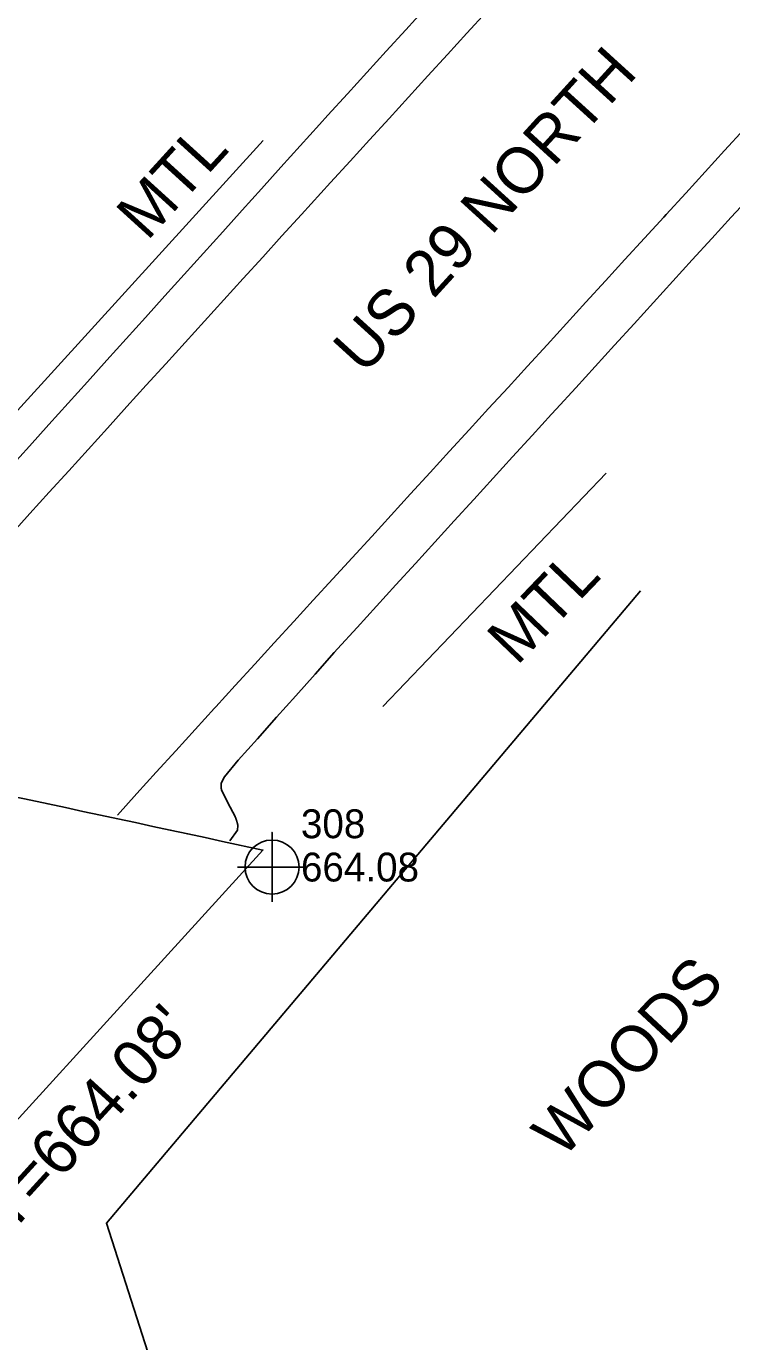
# Model space of a CAD drawing. Extents: x 1806071 to 1809844, y 912722 to 917035.
# Drawn here: x 1809224.9 to 1809286, y 916067.4 to 916181.4 of the extents above; entities that cross this region are included whole.
import ezdxf

# ---------------------------------------------------------------- set-up
doc = ezdxf.new("R2010")
doc.units = 0
for name, color, linetype in [('Exist Guardrail', 7, 'Continuous'), ('Exist Guardrail Text', 7, 'Continuous'), ('Exist Roads EOP', 7, 'Continuous'), ('Exist Roads EOP Text', 7, 'Continuous'), ('Exist Roads EOT', 7, 'Continuous'), ('Exist Structure Major Bridge Seat Cogo Elevation', 7, 'Continuous'), ('Exist Structure Major Bridge Seat Cogo Number', 7, 'Continuous'), ('Exist Structure Major Bridge Seat Cogo Point CELL', 7, 'Continuous'), ('Exist Structure Major Bridge Seat Top Elevation', 7, 'Continuous'), ('Exist Structure Major Deck Tunnel Box Culvert', 7, 'Continuous'), ('Exist Vegetation Woods Line', 7, 'Continuous'), ('Exist Vegetation Woods Line Text', 7, 'Continuous')]:
    doc.layers.add(name, color=color, linetype=linetype)

msp = doc.modelspace()

# ---------------------------------------------------------------- linework, layer by layer
at = {"layer": 'Exist Guardrail'}
msp.add_line((1809275.14, 916142.68), (1809255.81, 916122.48), dxfattribs=at)
msp.add_lwpolyline([(1809199.38, 916120.79), (1809211.9, 916134.7), (1809224.46, 916148.44), (1809245.44, 916171.5)], dxfattribs=at)
at = {"layer": 'Exist Roads EOP'}
for points in [[(1809259.46, 916182.95), (1809257.78, 916181.1), (1809256.1, 916179.25), (1809254.41, 916177.4), (1809252.73, 916175.56), (1809251.05, 916173.71), (1809250.31, 916172.9), (1809248.64, 916171.04), (1809246.97, 916169.19), (1809245.29, 916167.33), (1809243.62, 916165.47), (1809241.95, 916163.61), (1809240.27, 916161.76), (1809238.6, 916159.9), (1809236.93, 916158.04), (1809235.25, 916156.18), (1809233.58, 916154.33), (1809231.91, 916152.47), (1809230.24, 916150.61), (1809228.56, 916148.75), (1809226.89, 916146.9), (1809225.22, 916145.04), (1809223.54, 916143.18)], [(1809242.55, 916110.84), (1809243.22, 916111.76), (1809243.26, 916112.16), (1809243.26, 916112.17), (1809243.25, 916112.17), (1809243.25, 916112.17), (1809243.25, 916112.18), (1809243.25, 916112.18), (1809243.25, 916112.18), (1809243.25, 916112.19), (1809243.25, 916112.19), (1809243.25, 916112.19), (1809243.25, 916112.2), (1809243.25, 916112.2), (1809243.25, 916112.2), (1809243.25, 916112.2), (1809243.24, 916112.21), (1809243.24, 916112.21), (1809243.24, 916112.21), (1809243.24, 916112.22), (1809243.24, 916112.22), (1809243.24, 916112.22), (1809243.24, 916112.23), (1809243.24, 916112.23), (1809243.24, 916112.23), (1809243.24, 916112.24), (1809243.24, 916112.24), (1809243.24, 916112.24), (1809243.23, 916112.24), (1809243.23, 916112.25), (1809243.23, 916112.25), (1809243.23, 916112.25), (1809243.23, 916112.26), (1809243.23, 916112.26), (1809243.23, 916112.26), (1809243.23, 916112.27), (1809243.23, 916112.27), (1809243.23, 916112.27), (1809243.23, 916112.28), (1809243.23, 916112.28), (1809243.22, 916112.28), (1809243.22, 916112.28), (1809243.22, 916112.29), (1809243.22, 916112.29), (1809243.22, 916112.29), (1809243.22, 916112.3), (1809243.22, 916112.3), (1809243.22, 916112.3), (1809243.22, 916112.31), (1809243.22, 916112.31), (1809243.22, 916112.31), (1809243.22, 916112.32), (1809243.21, 916112.32), (1809243.21, 916112.32), (1809243.21, 916112.33), (1809243.21, 916112.33), (1809243.21, 916112.33), (1809243.21, 916112.33), (1809243.21, 916112.34), (1809243.21, 916112.34), (1809243.21, 916112.34), (1809243.21, 916112.35), (1809243.21, 916112.35), (1809243.21, 916112.35), (1809243.2, 916112.36), (1809243.2, 916112.36), (1809243.2, 916112.36), (1809243.2, 916112.37), (1809243.2, 916112.37), (1809243.2, 916112.37), (1809243.2, 916112.37), (1809243.2, 916112.38), (1809243.2, 916112.38), (1809243.2, 916112.38), (1809243.2, 916112.39), (1809243.2, 916112.39), (1809243.19, 916112.39), (1809243.19, 916112.4), (1809243.19, 916112.4), (1809243.19, 916112.4), (1809243.19, 916112.41), (1809243.19, 916112.41), (1809243.19, 916112.41), (1809243.19, 916112.41), (1809243.19, 916112.42), (1809243.19, 916112.42), (1809243.19, 916112.42), (1809243.19, 916112.43), (1809243.18, 916112.43), (1809243.18, 916112.43), (1809243.18, 916112.44), (1809243.18, 916112.44), (1809243.18, 916112.44), (1809243.18, 916112.45), (1809243.18, 916112.45), (1809243.18, 916112.45), (1809243.18, 916112.46), (1809243.18, 916112.46), (1809243.18, 916112.46), (1809243.18, 916112.46), (1809243.17, 916112.47), (1809243.17, 916112.47), (1809243.17, 916112.47), (1809243.17, 916112.48), (1809243.17, 916112.48), (1809243.17, 916112.48), (1809243.17, 916112.49), (1809243.17, 916112.49), (1809243.17, 916112.49), (1809243.17, 916112.5), (1809243.17, 916112.5), (1809243.17, 916112.5), (1809243.16, 916112.5), (1809243.16, 916112.51), (1809243.16, 916112.51), (1809243.16, 916112.51), (1809243.16, 916112.52), (1809243.16, 916112.52), (1809243.16, 916112.52), (1809243.16, 916112.53), (1809243.16, 916112.53), (1809243.16, 916112.53), (1809243.16, 916112.54), (1809243.16, 916112.54), (1809243.15, 916112.54), (1809243.15, 916112.54), (1809243.15, 916112.55), (1809243.15, 916112.55), (1809243.15, 916112.55), (1809243.15, 916112.56), (1809243.15, 916112.56), (1809243.15, 916112.56), (1809243.15, 916112.57), (1809243.14, 916112.57), (1809243.14, 916112.57), (1809243.14, 916112.58), (1809243.14, 916112.58), (1809243.14, 916112.58), (1809243.14, 916112.59), (1809243.14, 916112.59), (1809243.14, 916112.59), (1809243.13, 916112.6), (1809243.13, 916112.6), (1809243.13, 916112.6), (1809243.13, 916112.61), (1809243.13, 916112.61), (1809243.13, 916112.61), (1809243.13, 916112.62), (1809243.13, 916112.62), (1809243.13, 916112.62), (1809243.12, 916112.62), (1809243.12, 916112.63), (1809243.12, 916112.63), (1809243.12, 916112.63), (1809243.12, 916112.64), (1809243.12, 916112.64), (1809243.12, 916112.64), (1809243.12, 916112.65), (1809243.11, 916112.65), (1809243.11, 916112.65), (1809243.11, 916112.66), (1809243.11, 916112.66), (1809243.11, 916112.66), (1809243.11, 916112.67), (1809243.11, 916112.67), (1809243.11, 916112.67), (1809243.11, 916112.68), (1809243.1, 916112.68), (1809243.1, 916112.68), (1809243.1, 916112.69), (1809243.1, 916112.69), (1809243.1, 916112.69), (1809243.1, 916112.7), (1809243.1, 916112.7), (1809243.1, 916112.7), (1809243.1, 916112.71), (1809243.09, 916112.71), (1809243.09, 916112.71), (1809243.09, 916112.72), (1809243.09, 916112.72), (1809243.09, 916112.72), (1809243.09, 916112.72), (1809243.09, 916112.73), (1809243.09, 916112.73), (1809243.08, 916112.73), (1809243.08, 916112.74), (1809243.08, 916112.74), (1809243.08, 916112.74), (1809243.08, 916112.75), (1809243.08, 916112.75), (1809243.08, 916112.75), (1809243.08, 916112.76), (1809243.08, 916112.76), (1809243.07, 916112.76), (1809243.07, 916112.77), (1809243.07, 916112.77), (1809243.07, 916112.77), (1809243.07, 916112.78), (1809243.07, 916112.78), (1809243.07, 916112.78), (1809243.07, 916112.79), (1809243.06, 916112.79), (1809243.06, 916112.79), (1809243.06, 916112.8), (1809243.06, 916112.8), (1809243.06, 916112.8), (1809243.06, 916112.81), (1809243.06, 916112.81), (1809243.06, 916112.81), (1809243.06, 916112.82), (1809243.05, 916112.82), (1809243.05, 916112.82), (1809243.05, 916112.82), (1809243.05, 916112.83), (1809243.05, 916112.83), (1809243.05, 916112.83), (1809243.05, 916112.84), (1809243.05, 916112.84), (1809243.05, 916112.84), (1809243.04, 916112.85), (1809243.04, 916112.85), (1809243.04, 916112.85), (1809243.04, 916112.86), (1809243.04, 916112.86), (1809243.04, 916112.86), (1809243.04, 916112.87), (1809243.04, 916112.87), (1809243.03, 916112.87), (1809243.03, 916112.88), (1809243.03, 916112.88), (1809243.03, 916112.88), (1809243.03, 916112.89), (1809243.03, 916112.89), (1809243.03, 916112.89), (1809243.03, 916112.9), (1809243.03, 916112.9), (1809243.02, 916112.9), (1809243.02, 916112.91), (1809243.02, 916112.91), (1809243.02, 916112.91), (1809243.02, 916112.92), (1809243.02, 916112.92), (1809243.02, 916112.92), (1809243.02, 916112.92), (1809243.02, 916112.93), (1809242.37, 916114.13), (1809241.83, 916115.24), (1809241.83, 916115.24), (1809241.83, 916115.24), (1809241.83, 916115.24), (1809241.83, 916115.25), (1809241.83, 916115.25), (1809241.83, 916115.25), (1809241.83, 916115.25), (1809241.83, 916115.26), (1809241.83, 916115.26), (1809241.83, 916115.26), (1809241.83, 916115.26), (1809241.83, 916115.27), (1809241.83, 916115.27), (1809241.83, 916115.27), (1809241.83, 916115.27), (1809241.83, 916115.28), (1809241.82, 916115.28), (1809241.82, 916115.28), (1809241.82, 916115.28), (1809241.82, 916115.29), (1809241.82, 916115.29), (1809241.82, 916115.29), (1809241.82, 916115.29), (1809241.82, 916115.29), (1809241.82, 916115.3), (1809241.82, 916115.3), (1809241.82, 916115.3), (1809241.82, 916115.3), (1809241.82, 916115.31), (1809241.82, 916115.31), (1809241.82, 916115.31), (1809241.82, 916115.31), (1809241.82, 916115.32), (1809241.82, 916115.32), (1809241.82, 916115.32), (1809241.82, 916115.32), (1809241.82, 916115.33), (1809241.82, 916115.33), (1809241.82, 916115.33), (1809241.82, 916115.33), (1809241.82, 916115.34), (1809241.82, 916115.34), (1809241.82, 916115.34), (1809241.81, 916115.34), (1809241.81, 916115.35), (1809241.81, 916115.35), (1809241.81, 916115.35), (1809241.81, 916115.35), (1809241.81, 916115.36), (1809241.81, 916115.36), (1809241.81, 916115.36), (1809241.81, 916115.36), (1809241.81, 916115.37), (1809241.81, 916115.37), (1809241.81, 916115.37), (1809241.81, 916115.37), (1809241.81, 916115.38), (1809241.81, 916115.38), (1809241.81, 916115.38), (1809241.81, 916115.38), (1809241.81, 916115.39), (1809241.81, 916115.39), (1809241.81, 916115.39), (1809241.81, 916115.39), (1809241.81, 916115.4), (1809241.81, 916115.4), (1809241.81, 916115.4), (1809241.81, 916115.4), (1809241.8, 916115.41), (1809241.8, 916115.41), (1809241.8, 916115.41), (1809241.8, 916115.41), (1809241.8, 916115.42), (1809241.8, 916115.42), (1809241.8, 916115.42), (1809241.8, 916115.42), (1809241.8, 916115.43), (1809241.8, 916115.43), (1809241.8, 916115.43), (1809241.8, 916115.43), (1809241.8, 916115.44), (1809241.8, 916115.44), (1809241.8, 916115.44), (1809241.8, 916115.44), (1809241.8, 916115.45), (1809241.8, 916115.45), (1809241.8, 916115.45), (1809241.8, 916115.45), (1809241.8, 916115.45), (1809241.8, 916115.46), (1809241.8, 916115.46), (1809241.8, 916115.46), (1809241.8, 916115.46), (1809241.8, 916115.47), (1809241.79, 916115.47), (1809241.79, 916115.47), (1809241.79, 916115.47), (1809241.79, 916115.48), (1809241.79, 916115.48), (1809241.79, 916115.48), (1809241.79, 916115.48), (1809241.79, 916115.49), (1809241.79, 916115.49), (1809241.79, 916115.49), (1809241.79, 916115.49), (1809241.79, 916115.5), (1809241.79, 916115.5), (1809241.79, 916115.5), (1809241.79, 916115.5), (1809241.79, 916115.51), (1809241.79, 916115.51), (1809241.79, 916115.51), (1809241.79, 916115.51), (1809241.79, 916115.52), (1809241.79, 916115.52), (1809241.79, 916115.52), (1809241.79, 916115.52), (1809241.79, 916115.53), (1809241.79, 916115.53), (1809241.79, 916115.53), (1809241.79, 916115.53), (1809241.79, 916115.54), (1809241.79, 916115.54), (1809241.79, 916115.54), (1809241.79, 916115.54), (1809241.79, 916115.54), (1809241.79, 916115.55), (1809241.79, 916115.55), (1809241.79, 916115.55), (1809241.79, 916115.55), (1809241.79, 916115.56), (1809241.79, 916115.56), (1809241.79, 916115.56), (1809241.79, 916115.56), (1809241.79, 916115.57), (1809241.79, 916115.57), (1809241.79, 916115.57), (1809241.79, 916115.57), (1809241.79, 916115.58), (1809241.79, 916115.58), (1809241.79, 916115.58), (1809241.79, 916115.58), (1809241.79, 916115.58), (1809241.79, 916115.59), (1809241.79, 916115.59), (1809241.79, 916115.59), (1809241.79, 916115.59), (1809241.79, 916115.6), (1809241.79, 916115.6), (1809241.79, 916115.6), (1809241.79, 916115.6), (1809241.79, 916115.61), (1809241.79, 916115.61), (1809241.79, 916115.61), (1809241.79, 916115.61), (1809241.79, 916115.62), (1809241.79, 916115.62), (1809241.79, 916115.62), (1809241.79, 916115.62), (1809241.79, 916115.63), (1809241.79, 916115.63), (1809241.79, 916115.63), (1809241.79, 916115.63), (1809241.79, 916115.63), (1809241.79, 916115.64), (1809241.79, 916115.64), (1809241.8, 916115.64), (1809241.8, 916115.64), (1809241.8, 916115.65), (1809241.8, 916115.65), (1809241.8, 916115.65), (1809241.8, 916115.65), (1809241.8, 916115.66), (1809241.8, 916115.66), (1809241.8, 916115.66), (1809241.8, 916115.66), (1809241.8, 916115.67), (1809241.8, 916115.67), (1809241.8, 916115.67), (1809241.8, 916115.67), (1809241.8, 916115.67), (1809241.8, 916115.68), (1809241.8, 916115.68), (1809241.8, 916115.68), (1809241.8, 916115.68), (1809241.8, 916115.69), (1809241.8, 916115.69), (1809241.8, 916115.69), (1809241.8, 916115.69), (1809241.8, 916115.7), (1809241.8, 916115.7), (1809241.8, 916115.7), (1809241.8, 916115.7), (1809241.8, 916115.71), (1809241.8, 916115.71), (1809241.8, 916115.71), (1809241.8, 916115.71), (1809241.8, 916115.71), (1809241.8, 916115.72), (1809241.8, 916115.72), (1809241.8, 916115.72), (1809241.8, 916115.72), (1809241.8, 916115.73), (1809241.8, 916115.73), (1809241.8, 916115.73), (1809241.8, 916115.74), (1809241.8, 916115.74), (1809241.8, 916115.74), (1809241.8, 916115.74), (1809241.8, 916115.75), (1809241.8, 916115.75), (1809241.81, 916115.75), (1809241.81, 916115.75), (1809241.81, 916115.75), (1809241.81, 916115.76), (1809241.81, 916115.76), (1809241.81, 916115.76), (1809241.81, 916115.76), (1809241.81, 916115.77), (1809241.81, 916115.77), (1809241.81, 916115.77), (1809241.81, 916115.77), (1809241.81, 916115.78), (1809241.81, 916115.78), (1809241.81, 916115.78), (1809241.81, 916115.78), (1809241.81, 916115.79), (1809241.81, 916115.79), (1809241.81, 916115.8), (1809241.81, 916115.8), (1809241.81, 916115.8), (1809241.81, 916115.8), (1809241.81, 916115.8), (1809241.81, 916115.81), (1809241.81, 916115.81), (1809241.81, 916115.81), (1809241.81, 916115.81), (1809241.81, 916115.82), (1809241.81, 916115.82), (1809242.09, 916116.38), (1809243.28, 916117.81), (1809244.94, 916119.67), (1809246.6, 916121.54), (1809248.27, 916123.41), (1809249.93, 916125.27), (1809251.59, 916127.14), (1809251.88, 916127.46), (1809253.57, 916129.31), (1809255.25, 916131.16), (1809256.93, 916133.01), (1809258.62, 916134.85), (1809260.3, 916136.7), (1809261.99, 916138.55), (1809263.67, 916140.4), (1809265.35, 916142.24), (1809267.04, 916144.09), (1809268.72, 916145.94), (1809270.41, 916147.79), (1809270.81, 916148.23), (1809272.5, 916150.08), (1809274.18, 916151.93), (1809275.87, 916153.77), (1809277.55, 916155.62), (1809279.23, 916157.47), (1809280.92, 916159.31), (1809282.6, 916161.16), (1809284.29, 916163.01), (1809285.97, 916164.86), (1809287.66, 916166.7)]]:
    msp.add_lwpolyline(points, dxfattribs=at)
at = {"layer": 'Exist Roads EOT'}
for points in [[(1809264.77, 916182.65), (1809263.08, 916180.8), (1809261.39, 916178.95), (1809259.71, 916177.11), (1809258.02, 916175.26), (1809256.34, 916173.42), (1809254.65, 916171.57), (1809252.96, 916169.72), (1809251.28, 916167.88), (1809249.59, 916166.03), (1809248.75, 916165.11), (1809247.07, 916163.26), (1809245.4, 916161.41), (1809243.72, 916159.56), (1809242.04, 916157.71), (1809240.36, 916155.85), (1809238.68, 916154), (1809237, 916152.15), (1809235.32, 916150.3), (1809233.64, 916148.45), (1809231.96, 916146.59), (1809230.28, 916144.74), (1809228.6, 916142.89), (1809226.92, 916141.04), (1809225.24, 916139.19), (1809223.56, 916137.33)], [(1809232.83, 916113.07), (1809234.51, 916114.92), (1809236.19, 916116.78), (1809237.87, 916118.63), (1809239.55, 916120.48), (1809241.23, 916122.33), (1809241.34, 916122.45), (1809243.03, 916124.29), (1809244.71, 916126.14), (1809246.4, 916127.98), (1809248.09, 916129.83), (1809249.77, 916131.67), (1809251.46, 916133.52), (1809253.15, 916135.36), (1809254.84, 916137.21), (1809256.52, 916139.05), (1809258.21, 916140.9), (1809259.9, 916142.74), (1809261.58, 916144.59), (1809263.27, 916146.43), (1809264.96, 916148.28), (1809266.65, 916150.12), (1809268.33, 916151.97), (1809270.02, 916153.81), (1809271.71, 916155.66), (1809273.39, 916157.5), (1809275.08, 916159.35), (1809276.77, 916161.19), (1809278.45, 916163.04), (1809280.14, 916164.88), (1809280.34, 916165.1), (1809282.03, 916166.95), (1809283.72, 916168.79), (1809285.4, 916170.64), (1809287.09, 916172.48)]]:
    msp.add_lwpolyline(points, dxfattribs=at)
at = {"layer": 'Exist Structure Major Bridge Seat Cogo Point CELL'}
msp.add_lwpolyline([(1809243.21, 916108.56), (1809249.21, 916108.56), (1809246.21, 916108.56), (1809246.21, 916111.56), (1809246.21, 916105.56)], dxfattribs=at)
msp.add_circle((1809246.21, 916108.56), 2.34, dxfattribs=at)
at = {"layer": 'Exist Structure Major Deck Tunnel Box Culvert'}
msp.add_lwpolyline([(1809223.8, 916114.68), (1809225.31, 916114.36), (1809226.82, 916114.03), (1809228.33, 916113.71), (1809229.84, 916113.38), (1809231.35, 916113.06), (1809232.86, 916112.73), (1809234.38, 916112.41), (1809235.89, 916112.08), (1809237.4, 916111.76), (1809238.91, 916111.43), (1809240.42, 916111.11), (1809241.93, 916110.78), (1809245.42, 916110.03), (1809231.61, 916094.87), (1809218.15, 916080.08)], dxfattribs=at)
at = {"layer": 'Exist Vegetation Woods Line'}
msp.add_lwpolyline([(1809334.95, 916068.86), (1809238.55, 916056.89), (1809231.87, 916077.7), (1809278.12, 916132.48)], dxfattribs=at)

# ---------------------------------------------------------------- texts
at = {"layer": 'Exist Guardrail Text'}
for rotation, p in [(47.705, (1809235.4, 916162.74)), (46.2522, (1809267.42, 916125.94))]:
    msp.add_text('MTL', height=4, rotation=rotation, dxfattribs=at).set_placement(p)
at = {"layer": 'Exist Roads EOP Text'}
msp.add_text("US 29 NORTH    32' BST", height=4, rotation=47.6886, dxfattribs=at).set_placement((1809254.17, 916151.11))
at = {"layer": 'Exist Structure Major Bridge Seat Cogo Elevation'}
msp.add_text('664.08', height=2.5, dxfattribs=at).set_placement((1809248.71, 916107.31))
at = {"layer": 'Exist Structure Major Bridge Seat Cogo Number'}
msp.add_text('308', height=2.5, dxfattribs=at).set_placement((1809248.71, 916111.06))
at = {"layer": 'Exist Structure Major Bridge Seat Top Elevation'}
msp.add_text("SEAT=664.08'", height=4, rotation=47.6571, dxfattribs=at).set_placement((1809216.35, 916068.82))
at = {"layer": 'Exist Vegetation Woods Line Text'}
msp.add_text('WOODS', height=4, rotation=47.0932, dxfattribs=at).set_placement((1809271.37, 916083.21))

doc.saveas('drawing.dxf')
